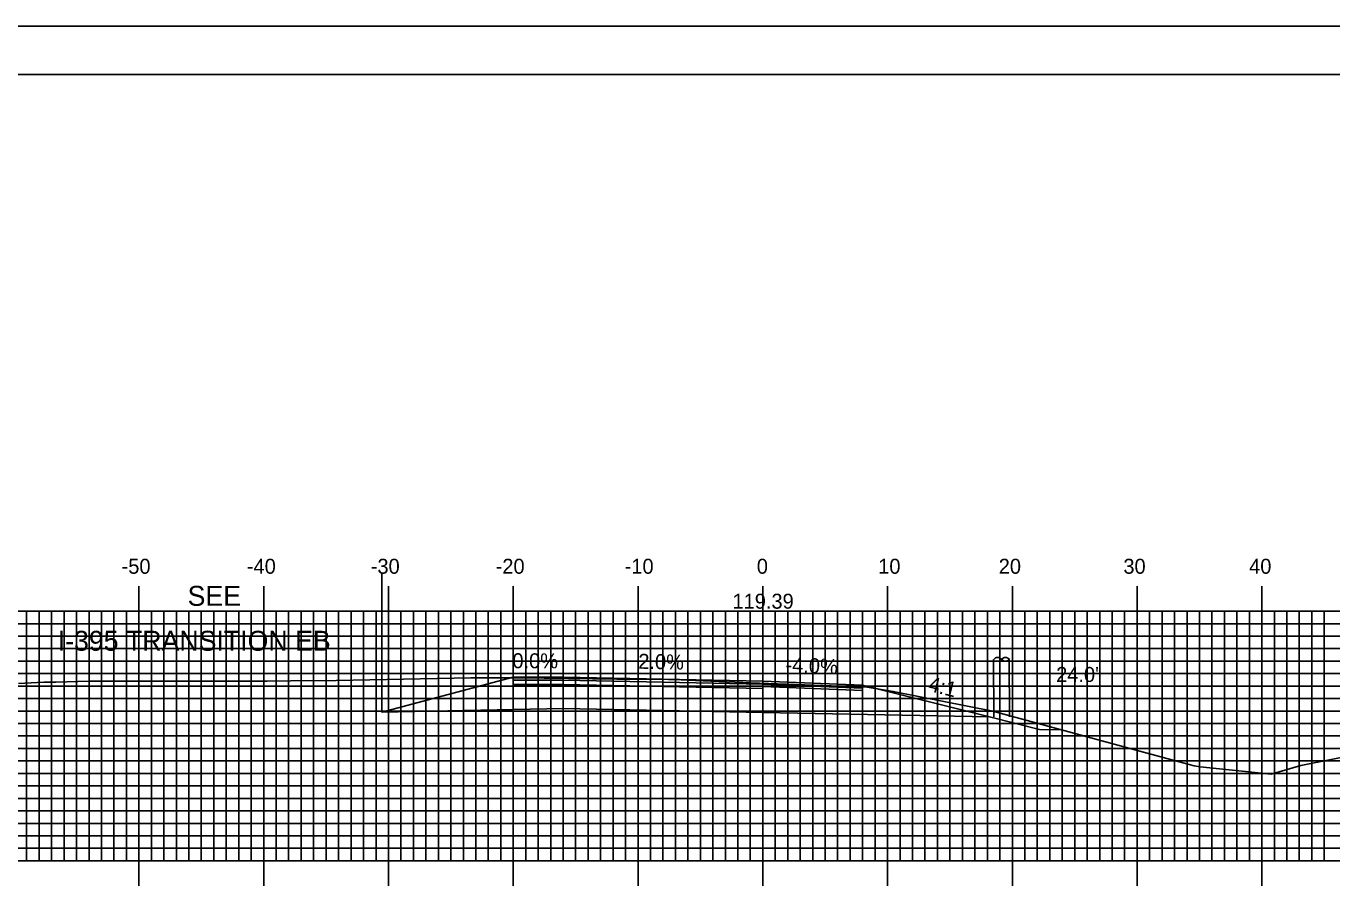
# Model space of a CAD drawing. Extents: x 844536 to 844879, y 363538 to 363758.
# Drawn here: x 844642.9 to 844747.6, y 363688.2 to 363757.6 of the extents above; entities that cross this region are included whole.
import ezdxf

# ---------------------------------------------------------------- set-up
doc = ezdxf.new("R2010")
doc.units = 0
for name, color, linetype in [('ANNOTATION', 7, 'Continuous'), ('BORDER', 7, 'Continuous'), ('D_Roadway_Centerline_Text', 7, 'Continuous'), ('D_Roadway_Edge_Shoulder', 7, 'Continuous'), ('D_Roadway_Edge_TW', 7, 'Continuous'), ('D_Roadway_FinishedGrade', 7, 'Continuous'), ('D_Roadway_Pavement', 7, 'Continuous'), ('D_Roadway_SlopeLines', 7, 'Continuous'), ('D_Roadway_SubGrade', 7, 'Continuous'), ('D_Text_Standard', 7, 'Continuous'), ('H_V ANNOTATION', 7, 'Continuous'), ('M_Roadway_Centerline', 7, 'Continuous'), ('MAJOR', 7, 'Continuous'), ('MINOR', 7, 'Continuous'), ('PLOT BOUNDARY', 7, 'Continuous'), ('S_Roadway_Centerline', 7, 'Continuous'), ('S_Utilities_Pole_StreetLight', 7, 'Continuous')]:
    doc.layers.add(name, color=color, linetype=linetype)

msp = doc.modelspace()

# ---------------------------------------------------------------- linework, layer by layer
at = {"layer": 'BORDER'}
msp.add_lwpolyline([(844552.36, 363543.72), (844872.36, 363543.72), (844872.36, 363753.72), (844552.36, 363753.72)], close=True, dxfattribs=at)
at = {"layer": 'D_Roadway_Edge_Shoulder'}
msp.add_lwpolyline([(844701.96, 363705.11), (844709.96, 363704.79), (844709.96, 363704.54), (844701.96, 363704.86)], close=True, dxfattribs=at)
at = {"layer": 'D_Roadway_Edge_TW'}
msp.add_lwpolyline([(844685.96, 363705.43), (844701.96, 363705.11), (844701.96, 363704.86), (844685.96, 363705.18)], close=True, dxfattribs=at)
at = {"layer": 'D_Roadway_FinishedGrade'}
for p, q in [((844685.96, 363705.43), (844681.96, 363705.43)), ((844685.96, 363705.18), (844681.96, 363705.18)), ((844685.96, 363702.93), (844671.44, 363702.64))]:
    msp.add_line(p, q, dxfattribs=at)
for points in [[(844685.96, 363704.85), (844681.96, 363704.85), (844681.96, 363705.43), (844671.44, 363702.64)], [(844720.14, 363702.25), (844724.14, 363701.25), (844725.92, 363701.21)]]:
    msp.add_lwpolyline(points, dxfattribs=at)
at = {"layer": 'D_Roadway_Pavement'}
for points in [[(844685.96, 363705.18), (844701.96, 363704.86), (844701.96, 363704.53), (844685.96, 363704.85)], [(844701.96, 363704.86), (844709.96, 363704.54), (844709.96, 363704.37), (844701.96, 363704.69)]]:
    msp.add_lwpolyline(points, close=True, dxfattribs=at)
msp.add_lwpolyline([(844701.96, 363704.86), (844701.96, 363704.53)], dxfattribs=at)
msp.add_lwpolyline([(844701.96, 363704.86), (844701.96, 363704.53)], dxfattribs=at)
at = {"layer": 'D_Roadway_SlopeLines'}
msp.add_lwpolyline([(844709.96, 363704.79), (844711.16, 363704.49)], dxfattribs=at)
at = {"layer": 'D_Roadway_SubGrade'}
msp.add_line((844671.44, 363713.74), (844671.44, 363702.64), dxfattribs=at)
for points in [[(844685.96, 363704.85), (844701.96, 363704.53), (844701.96, 363702.61), (844685.96, 363702.93)], [(844701.96, 363704.53), (844701.96, 363704.86), (844709.96, 363704.54), (844709.96, 363704.79), (844720.14, 363702.25), (844701.96, 363702.61)]]:
    msp.add_lwpolyline(points, close=True, dxfattribs=at)
at = {"layer": 'MAJOR'}
for p, q in [((844651.96, 363712.73), (844651.96, 363710.72)), ((844661.96, 363712.73), (844661.96, 363710.72)), ((844671.96, 363712.73), (844671.96, 363710.72)), ((844681.96, 363712.73), (844681.96, 363710.72)), ((844691.96, 363712.73), (844691.96, 363710.72)), ((844701.96, 363712.73), (844701.96, 363710.72)), ((844711.96, 363712.73), (844711.96, 363710.72)), ((844721.96, 363712.73), (844721.96, 363710.72)), ((844731.96, 363712.73), (844731.96, 363710.72)), ((844741.96, 363712.73), (844741.96, 363710.72)), ((844561.96, 363710.72), (844841.96, 363710.72)), ((844561.96, 363710.72), (844841.96, 363710.72)), ((844651.96, 363690.72), (844651.96, 363710.72)), ((844661.96, 363690.72), (844661.96, 363710.72)), ((844671.96, 363690.72), (844671.96, 363710.72)), ((844681.96, 363690.72), (844681.96, 363710.72)), ((844691.96, 363690.72), (844691.96, 363710.72)), ((844701.96, 363690.72), (844701.96, 363710.72)), ((844711.96, 363690.72), (844711.96, 363710.72)), ((844721.96, 363690.72), (844721.96, 363710.72)), ((844731.96, 363690.72), (844731.96, 363710.72)), ((844741.96, 363690.72), (844741.96, 363710.72)), ((844561.96, 363705.72), (844841.96, 363705.72)), ((844561.96, 363700.72), (844841.96, 363700.72)), ((844561.96, 363695.72), (844841.96, 363695.72)), ((844561.96, 363690.72), (844841.96, 363690.72)), ((844561.96, 363690.72), (844841.96, 363690.72)), ((844651.96, 363688.72), (844651.96, 363690.72)), ((844661.96, 363688.72), (844661.96, 363690.72)), ((844671.96, 363688.72), (844671.96, 363690.72)), ((844681.96, 363688.72), (844681.96, 363690.72)), ((844691.96, 363688.72), (844691.96, 363690.72)), ((844701.96, 363688.72), (844701.96, 363690.72)), ((844711.96, 363688.72), (844711.96, 363690.72)), ((844721.96, 363688.72), (844721.96, 363690.72)), ((844731.96, 363688.72), (844731.96, 363690.72)), ((844741.96, 363688.72), (844741.96, 363690.72))]:
    msp.add_line(p, q, dxfattribs=at)
at = {"layer": 'MINOR'}
for p, q in [((844642.96, 363690.72), (844642.96, 363710.72)), ((844643.96, 363690.72), (844643.96, 363710.72)), ((844644.96, 363690.72), (844644.96, 363710.72)), ((844645.96, 363690.72), (844645.96, 363710.72)), ((844646.96, 363690.72), (844646.96, 363710.72)), ((844647.96, 363690.72), (844647.96, 363710.72)), ((844648.96, 363690.72), (844648.96, 363710.72)), ((844649.96, 363690.72), (844649.96, 363710.72)), ((844650.96, 363690.72), (844650.96, 363710.72)), ((844652.96, 363690.72), (844652.96, 363710.72)), ((844653.96, 363690.72), (844653.96, 363710.72)), ((844654.96, 363690.72), (844654.96, 363710.72)), ((844655.96, 363690.72), (844655.96, 363710.72)), ((844656.96, 363690.72), (844656.96, 363710.72)), ((844657.96, 363690.72), (844657.96, 363710.72)), ((844658.96, 363690.72), (844658.96, 363710.72)), ((844659.96, 363690.72), (844659.96, 363710.72)), ((844660.96, 363690.72), (844660.96, 363710.72)), ((844662.96, 363690.72), (844662.96, 363710.72)), ((844663.96, 363690.72), (844663.96, 363710.72)), ((844664.96, 363690.72), (844664.96, 363710.72)), ((844665.96, 363690.72), (844665.96, 363710.72)), ((844666.96, 363690.72), (844666.96, 363710.72)), ((844667.96, 363690.72), (844667.96, 363710.72)), ((844668.96, 363690.72), (844668.96, 363710.72)), ((844669.96, 363690.72), (844669.96, 363710.72)), ((844670.96, 363690.72), (844670.96, 363710.72)), ((844672.96, 363690.72), (844672.96, 363710.72)), ((844673.96, 363690.72), (844673.96, 363710.72)), ((844674.96, 363690.72), (844674.96, 363710.72)), ((844675.96, 363690.72), (844675.96, 363710.72)), ((844676.96, 363690.72), (844676.96, 363710.72)), ((844677.96, 363690.72), (844677.96, 363710.72)), ((844678.96, 363690.72), (844678.96, 363710.72)), ((844679.96, 363690.72), (844679.96, 363710.72)), ((844680.96, 363690.72), (844680.96, 363710.72)), ((844682.96, 363690.72), (844682.96, 363710.72)), ((844683.96, 363690.72), (844683.96, 363710.72)), ((844684.96, 363690.72), (844684.96, 363710.72)), ((844685.96, 363690.72), (844685.96, 363710.72)), ((844686.96, 363690.72), (844686.96, 363710.72)), ((844687.96, 363690.72), (844687.96, 363710.72)), ((844688.96, 363690.72), (844688.96, 363710.72)), ((844689.96, 363690.72), (844689.96, 363710.72)), ((844690.96, 363690.72), (844690.96, 363710.72)), ((844692.96, 363690.72), (844692.96, 363710.72)), ((844693.96, 363690.72), (844693.96, 363710.72)), ((844694.96, 363690.72), (844694.96, 363710.72)), ((844695.96, 363690.72), (844695.96, 363710.72)), ((844696.96, 363690.72), (844696.96, 363710.72)), ((844697.96, 363690.72), (844697.96, 363710.72)), ((844698.96, 363690.72), (844698.96, 363710.72)), ((844699.96, 363690.72), (844699.96, 363710.72)), ((844700.96, 363690.72), (844700.96, 363710.72)), ((844702.96, 363690.72), (844702.96, 363710.72)), ((844703.96, 363690.72), (844703.96, 363710.72)), ((844704.96, 363690.72), (844704.96, 363710.72)), ((844705.96, 363690.72), (844705.96, 363710.72)), ((844706.96, 363690.72), (844706.96, 363710.72)), ((844707.96, 363690.72), (844707.96, 363710.72)), ((844708.96, 363690.72), (844708.96, 363710.72)), ((844709.96, 363690.72), (844709.96, 363710.72)), ((844710.96, 363690.72), (844710.96, 363710.72)), ((844712.96, 363690.72), (844712.96, 363710.72)), ((844713.96, 363690.72), (844713.96, 363710.72)), ((844714.96, 363690.72), (844714.96, 363710.72)), ((844715.96, 363690.72), (844715.96, 363710.72)), ((844716.96, 363690.72), (844716.96, 363710.72)), ((844717.96, 363690.72), (844717.96, 363710.72)), ((844718.96, 363690.72), (844718.96, 363710.72)), ((844719.96, 363690.72), (844719.96, 363710.72)), ((844720.96, 363690.72), (844720.96, 363710.72)), ((844722.96, 363690.72), (844722.96, 363710.72)), ((844723.96, 363690.72), (844723.96, 363710.72)), ((844724.96, 363690.72), (844724.96, 363710.72)), ((844725.96, 363690.72), (844725.96, 363710.72)), ((844726.96, 363690.72), (844726.96, 363710.72)), ((844727.96, 363690.72), (844727.96, 363710.72)), ((844728.96, 363690.72), (844728.96, 363710.72)), ((844729.96, 363690.72), (844729.96, 363710.72)), ((844730.96, 363690.72), (844730.96, 363710.72)), ((844732.96, 363690.72), (844732.96, 363710.72)), ((844733.96, 363690.72), (844733.96, 363710.72)), ((844734.96, 363690.72), (844734.96, 363710.72)), ((844735.96, 363690.72), (844735.96, 363710.72)), ((844736.96, 363690.72), (844736.96, 363710.72)), ((844737.96, 363690.72), (844737.96, 363710.72)), ((844738.96, 363690.72), (844738.96, 363710.72)), ((844739.96, 363690.72), (844739.96, 363710.72)), ((844740.96, 363690.72), (844740.96, 363710.72)), ((844742.96, 363690.72), (844742.96, 363710.72)), ((844743.96, 363690.72), (844743.96, 363710.72)), ((844744.96, 363690.72), (844744.96, 363710.72)), ((844745.96, 363690.72), (844745.96, 363710.72)), ((844746.96, 363690.72), (844746.96, 363710.72)), ((844561.96, 363709.72), (844841.96, 363709.72)), ((844561.96, 363708.72), (844841.96, 363708.72)), ((844561.96, 363707.72), (844841.96, 363707.72)), ((844561.96, 363706.72), (844841.96, 363706.72)), ((844561.96, 363704.72), (844841.96, 363704.72)), ((844561.96, 363703.72), (844841.96, 363703.72)), ((844561.96, 363702.72), (844841.96, 363702.72)), ((844561.96, 363701.72), (844841.96, 363701.72)), ((844561.96, 363699.72), (844841.96, 363699.72)), ((844561.96, 363698.72), (844841.96, 363698.72)), ((844561.96, 363697.72), (844841.96, 363697.72)), ((844561.96, 363696.72), (844841.96, 363696.72)), ((844561.96, 363694.72), (844841.96, 363694.72)), ((844561.96, 363693.72), (844841.96, 363693.72)), ((844561.96, 363692.72), (844841.96, 363692.72)), ((844561.96, 363691.72), (844841.96, 363691.72))]:
    msp.add_line(p, q, dxfattribs=at)
at = {"layer": 'PLOT BOUNDARY'}
msp.add_lwpolyline([(844536.18, 363537.6), (844876.18, 363537.6), (844876.18, 363757.6), (844536.18, 363757.6)], close=True, dxfattribs=at)
at = {"layer": 'S_Roadway_Centerline'}
msp.add_lwpolyline([(844642.31, 363704.92), (844644.33, 363705.02), (844645.3, 363705.03), (844647.95, 363705.1), (844662.24, 363705.11), (844664.13, 363705.13), (844667.76, 363705.16), (844678.55, 363705.37), (844682.49, 363705.39), (844690.27, 363705.27), (844694.41, 363705.24), (844694.51, 363705.25), (844694.9, 363705.24), (844695.92, 363705.18), (844701.62, 363704.94), (844701.7, 363704.94), (844710.32, 363704.62), (844712.42, 363704.29), (844720.39, 363702.71), (844734.93, 363698.76), (844736.54, 363698.32), (844737.01, 363698.24), (844742.7, 363697.65), (844745.08, 363698.35), (844750.07, 363699.35)], dxfattribs=at)
at = {"layer": 'S_Utilities_Pole_StreetLight'}
for p, q in [((844720.47, 363702.25), (844720.46, 363706.86)), ((844720.47, 363706.86), (844720.62, 363706.98)), ((844720.93, 363706.98), (844721.09, 363706.86)), ((844721.25, 363706.98), (844721.09, 363706.86)), ((844721.09, 363706.86), (844721.25, 363706.75)), ((844721.72, 363706.86), (844721.56, 363706.98)), ((844721.56, 363706.75), (844721.72, 363706.86)), ((844721.72, 363702.25), (844721.71, 363706.86))]:
    msp.add_line(p, q, dxfattribs=at)
for centre, start, end in [((844720.78, 363706.75), 90, 125.2644), ((844720.78, 363706.75), 54.7356, 90), ((844721.4, 363706.75), 90, 125.2644), ((844721.4, 363706.98), 234.7356, 270), ((844721.4, 363706.75), 54.7356, 90), ((844721.4, 363706.98), 270, 305.2644)]:
    msp.add_arc(centre, 0.271, start, end, dxfattribs=at)

# ---------------------------------------------------------------- texts
at = {"layer": 'ANNOTATION'}
for s, p in [('SEE', (844655.86, 363711.15)), ('I-395 TRANSITION EB', (844645.45, 363707.55))]:
    msp.add_text(s, height=1.6, dxfattribs=at).set_placement(p)
for s, rotation, p in [('0.0%', 359.8447, (844681.89, 363706.15)), ('2.0%', 358.8542, (844691.97, 363706.11)), ('-4.0%', 357.7094, (844703.76, 363705.84)), ('4:1', 345.9638, (844715.15, 363704.35))]:
    msp.add_text(s, height=1.2, rotation=rotation, dxfattribs=at).set_placement(p)
at = {"layer": 'D_Roadway_Centerline_Text'}
msp.add_text('119.39', height=1.2, dxfattribs=at).set_placement((844699.53, 363710.92))
at = {"layer": 'D_Text_Standard'}
msp.add_text("24.0'", height=1.2, dxfattribs=at).set_placement((844725.47, 363705.05))
at = {"layer": 'H_V ANNOTATION'}
for s, p in [('-50', (844650.57, 363713.72)), ('-40', (844660.61, 363713.72)), ('-30', (844670.54, 363713.72)), ('-20', (844680.55, 363713.72)), ('-10', (844690.89, 363713.72)), ('0', (844701.48, 363713.72)), ('10', (844711.21, 363713.72)), ('20', (844720.87, 363713.72)), ('30', (844730.86, 363713.72)), ('40', (844740.94, 363713.72))]:
    msp.add_text(s, height=1.2, dxfattribs=at).set_placement(p)
at = {"layer": 'M_Roadway_Centerline'}
for s, p in [('C', (844644.33, 363705.02)), ('L', (844644.33, 363705.01)), ('C', (844694.5, 363705.25)), ('L', (844694.51, 363705.24))]:
    msp.add_text(s, height=0.0146, dxfattribs=at).set_placement(p)

doc.saveas('drawing.dxf')
